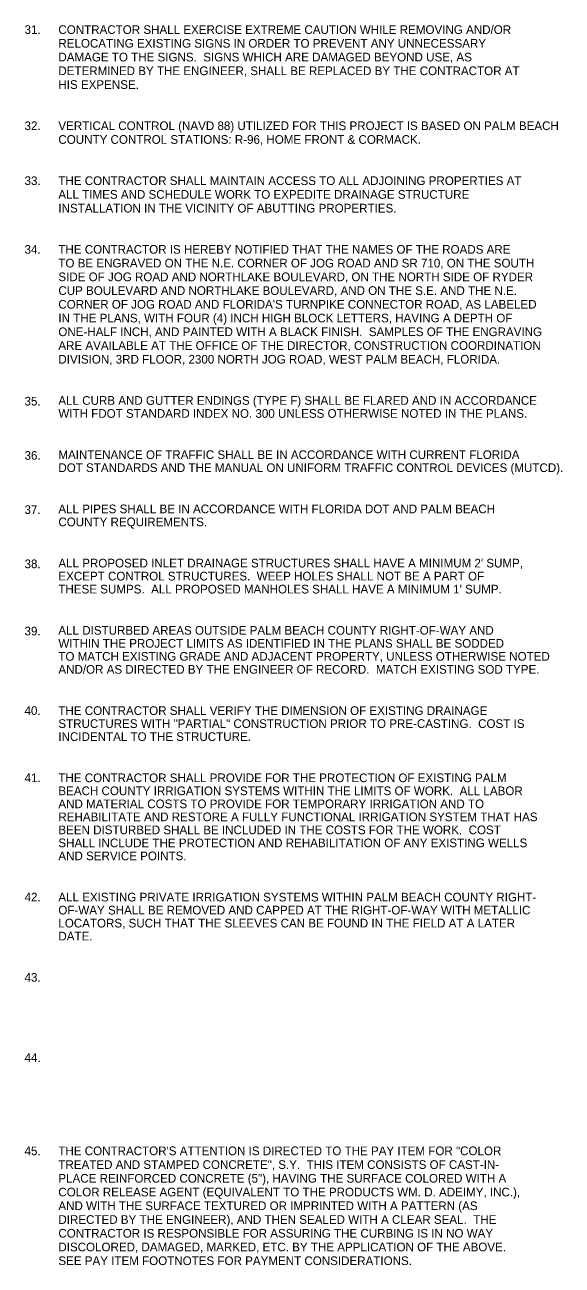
# Model space of a CAD drawing. Extents: x 783907 to 784590, y 832093 to 832609.
# Drawn here: x 784303.6 to 784340.8, y 832518.9 to 832604.7 of the extents above; entities that cross this region are included whole.
import ezdxf

# ---------------------------------------------------------------- set-up
doc = ezdxf.new("R2010")
doc.units = 0
doc.layers.add('Default', color=7, linetype='Continuous')

msp = doc.modelspace()

# ---------------------------------------------------------------- texts
at = {"layer": 'Default'}
for s, p in [('31.', (784303.539, 832604.024)), ('CONTRACTOR SHALL EXERCISE EXTREME CAUTION WHILE REMOVING AND/OR', (784305.882, 832604.024)), ('RELOCATING EXISTING SIGNS IN ORDER TO PREVENT ANY UNNECESSARY', (784305.882, 832603.074)), ('DAMAGE TO THE SIGNS.  SIGNS WHICH ARE DAMAGED BEYOND USE, AS', (784305.882, 832602.124)), ('DETERMINED BY THE ENGINEER, SHALL BE REPLACED BY THE CONTRACTOR AT', (784305.882, 832601.174)), ('HIS EXPENSE.', (784305.882, 832600.224)), ('32.', (784303.539, 832597.374)), ('VERTICAL CONTROL (NAVD 88) UTILIZED FOR THIS PROJECT IS BASED ON PALM BEACH', (784305.882, 832597.374)), ('COUNTY CONTROL STATIONS: R-96, HOME FRONT & CORMACK.', (784305.882, 832596.424)), ('33.', (784303.539, 832593.574)), ('THE CONTRACTOR SHALL MAINTAIN ACCESS TO ALL ADJOINING PROPERTIES AT', (784305.882, 832593.574)), ('ALL TIMES AND SCHEDULE WORK TO EXPEDITE DRAINAGE STRUCTURE', (784305.882, 832592.624)), ('INSTALLATION IN THE VICINITY OF ABUTTING PROPERTIES.', (784305.882, 832591.674)), ('34.', (784303.539, 832588.824)), ('THE CONTRACTOR IS HEREBY NOTIFIED THAT THE NAMES OF THE ROADS ARE', (784305.882, 832588.824)), ('TO BE ENGRAVED ON THE N.E. CORNER OF JOG ROAD AND SR 710, ON THE SOUTH', (784305.882, 832587.874)), ('SIDE OF JOG ROAD AND NORTHLAKE BOULEVARD, ON THE NORTH SIDE OF RYDER', (784305.882, 832586.924)), ('CUP BOULEVARD AND NORTHLAKE BOULEVARD, AND ON THE S.E. AND THE N.E.', (784305.882, 832585.974)), ("CORNER OF JOG ROAD AND FLORIDA'S TURNPIKE CONNECTOR ROAD, AS LABELED", (784305.882, 832585.024)), ('IN THE PLANS, WITH FOUR (4) INCH HIGH BLOCK LETTERS, HAVING A DEPTH OF', (784305.882, 832584.074)), ('ONE-HALF INCH, AND PAINTED WITH A BLACK FINISH.  SAMPLES OF THE ENGRAVING', (784305.882, 832583.124)), ('ARE AVAILABLE AT THE OFFICE OF THE DIRECTOR, CONSTRUCTION COORDINATION', (784305.882, 832582.174)), ('DIVISION, 3RD FLOOR, 2300 NORTH JOG ROAD, WEST PALM BEACH, FLORIDA. ', (784305.882, 832581.224)), ('35.', (784303.539, 832578.324)), ('ALL CURB AND GUTTER ENDINGS (TYPE F) SHALL BE FLARED AND IN ACCORDANCE', (784305.882, 832578.374)), ('WITH FDOT STANDARD INDEX NO. 300 UNLESS OTHERWISE NOTED IN THE PLANS.', (784305.882, 832577.474)), ('36.', (784303.539, 832574.574)), ('MAINTENANCE OF TRAFFIC SHALL BE IN ACCORDANCE WITH CURRENT FLORIDA ', (784305.882, 832574.624)), ('DOT STANDARDS AND THE MANUAL ON UNIFORM TRAFFIC CONTROL DEVICES (MUTCD).', (784305.882, 832573.724)), ('37.', (784303.539, 832570.824)), ('ALL PIPES SHALL BE IN ACCORDANCE WITH FLORIDA DOT AND PALM BEACH', (784305.882, 832570.874)), ('COUNTY REQUIREMENTS.', (784305.882, 832569.974)), ('38.', (784303.539, 832567.074)), ("ALL PROPOSED INLET DRAINAGE STRUCTURES SHALL HAVE A MINIMUM 2' SUMP, ", (784305.882, 832567.124)), ('EXCEPT CONTROL STRUCTURES.  WEEP HOLES SHALL NOT BE A PART OF', (784305.882, 832566.224)), ("THESE SUMPS.  ALL PROPOSED MANHOLES SHALL HAVE A MINIMUM 1' SUMP.", (784305.882, 832565.324)), ('39.', (784303.539, 832562.424)), ('ALL DISTURBED AREAS OUTSIDE PALM BEACH COUNTY RIGHT-OF-WAY AND', (784305.882, 832562.474)), ('WITHIN THE PROJECT LIMITS AS IDENTIFIED IN THE PLANS SHALL BE SODDED', (784305.882, 832561.574)), ('TO MATCH EXISTING GRADE AND ADJACENT PROPERTY, UNLESS OTHERWISE NOTED', (784305.882, 832560.674)), ('AND/OR AS DIRECTED BY THE ENGINEER OF RECORD.  MATCH EXISTING SOD TYPE.', (784305.882, 832559.774)), ('40.', (784303.539, 832556.924)), ('THE CONTRACTOR SHALL VERIFY THE DIMENSION OF EXISTING DRAINAGE', (784305.882, 832556.924)), ('STRUCTURES WITH "PARTIAL" CONSTRUCTION PRIOR TO PRE-CASTING.  COST IS', (784305.882, 832556.024)), ('INCIDENTAL TO THE STRUCTURE.', (784305.882, 832555.124)), ('41.', (784303.539, 832552.274)), ('THE CONTRACTOR SHALL PROVIDE FOR THE PROTECTION OF EXISTING PALM', (784305.882, 832552.274)), ('BEACH COUNTY IRRIGATION SYSTEMS WITHIN THE LIMITS OF WORK.  ALL LABOR', (784305.882, 832551.374)), ('AND MATERIAL COSTS TO PROVIDE FOR TEMPORARY IRRIGATION AND TO', (784305.882, 832550.474)), ('REHABILITATE AND RESTORE A FULLY FUNCTIONAL IRRIGATION SYSTEM THAT HAS', (784305.882, 832549.574)), ('BEEN DISTURBED SHALL BE INCLUDED IN THE COSTS FOR THE WORK.  COST', (784305.882, 832548.674)), ('SHALL INCLUDE THE PROTECTION AND REHABILITATION OF ANY EXISTING WELLS', (784305.882, 832547.774)), ('AND SERVICE POINTS.', (784305.882, 832546.874)), ('42.', (784303.539, 832544.024)), ('ALL EXISTING PRIVATE IRRIGATION SYSTEMS WITHIN PALM BEACH COUNTY RIGHT-', (784305.882, 832544.024)), ('OF-WAY SHALL BE REMOVED AND CAPPED AT THE RIGHT-OF-WAY WITH METALLIC', (784305.882, 832543.124)), ('LOCATORS, SUCH THAT THE SLEEVES CAN BE FOUND IN THE FIELD AT A LATER', (784305.882, 832542.224)), ('DATE.', (784305.882, 832541.324)), ('43.', (784303.539, 832538.474)), ('44.', (784303.539, 832532.924)), ('45.', (784303.539, 832526.474)), ('THE CONTRACTOR\'S ATTENTION IS DIRECTED TO THE PAY ITEM FOR "COLOR ', (784305.882, 832526.474)), ('TREATED AND STAMPED CONCRETE", S.Y.  THIS ITEM CONSISTS OF CAST-IN-', (784305.882, 832525.524)), ('PLACE REINFORCED CONCRETE (5"), HAVING THE SURFACE COLORED WITH A', (784305.882, 832524.574)), ('COLOR RELEASE AGENT (EQUIVALENT TO THE PRODUCTS WM. D. ADEIMY, INC.), ', (784305.882, 832523.624)), ('AND WITH THE SURFACE TEXTURED OR IMPRINTED WITH A PATTERN (AS ', (784305.882, 832522.674)), ('DIRECTED BY THE ENGINEER), AND THEN SEALED WITH A CLEAR SEAL.  THE ', (784305.882, 832521.724)), ('CONTRACTOR IS RESPONSIBLE FOR ASSURING THE CURBING IS IN NO WAY ', (784305.882, 832520.774)), ('DISCOLORED, DAMAGED, MARKED, ETC. BY THE APPLICATION OF THE ABOVE.  ', (784305.882, 832519.824)), ('SEE PAY ITEM FOOTNOTES FOR PAYMENT CONSIDERATIONS.', (784305.882, 832518.874))]:
    msp.add_text(s, height=0.6, dxfattribs=at).set_placement(p)

doc.saveas('drawing.dxf')
